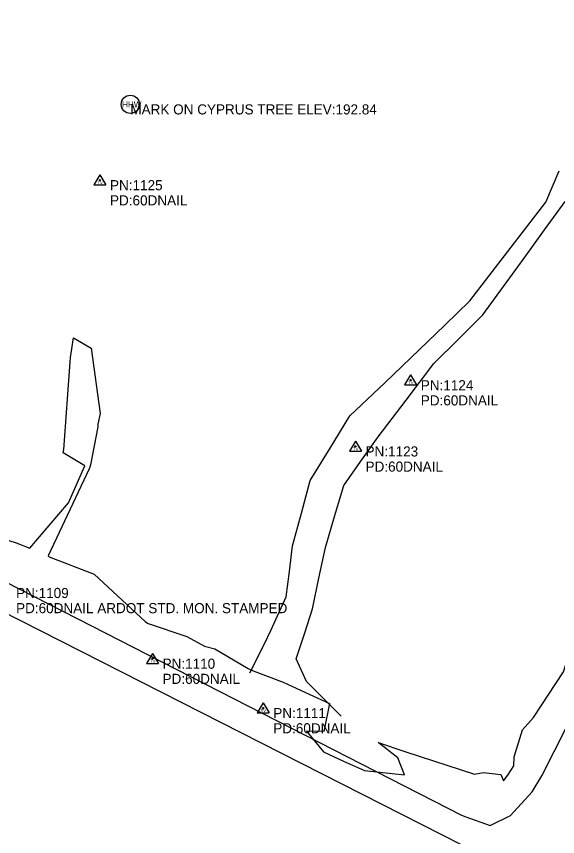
# Model space of a CAD drawing. Extents: x 1383673 to 1386849, y 1973501 to 1978801.
# Drawn here: x 1384772.1 to 1385039.6, y 1974564.7 to 1974970.6 of the extents above; entities that cross this region are included whole.
import ezdxf

# ---------------------------------------------------------------- set-up
doc = ezdxf.new("R2010")
doc.units = 0
for name, color, linetype in [('Level 8', 7, 'Continuous'), ('R_Draft', 7, 'Continuous'), ('R_Driveway', 7, 'Continuous'), ('R_Proposed Const Limits', 7, 'Continuous'), ('R_Proposed Road', 7, 'Continuous'), ('R_Shld', 7, 'Continuous'), ('S_STREAM', 7, 'Continuous')]:
    doc.layers.add(name, color=color, linetype=linetype)

msp = doc.modelspace()

# ---------------------------------------------------------------- linework, layer by layer
at = {"layer": 'Level 8'}
for p, q in [((1384813.33, 1974892.22), (1384810.32, 1974887.26)), ((1384813.33, 1974892.22), (1384816.27, 1974887.26)), ((1384810.32, 1974887.26), (1384816.27, 1974887.26)), ((1384966.98, 1974793.22), (1384963.97, 1974788.27)), ((1384966.98, 1974793.22), (1384969.93, 1974788.27)), ((1384963.97, 1974788.27), (1384969.93, 1974788.27)), ((1384939.68, 1974760.45), (1384936.67, 1974755.49)), ((1384939.68, 1974760.45), (1384942.63, 1974755.49)), ((1384936.67, 1974755.49), (1384942.63, 1974755.49)), ((1384839.32, 1974655.41), (1384836.31, 1974650.45)), ((1384839.32, 1974655.41), (1384842.27, 1974650.45)), ((1384836.31, 1974650.45), (1384842.27, 1974650.45)), ((1384894.06, 1974630.96), (1384891.05, 1974626)), ((1384894.06, 1974630.96), (1384897.01, 1974626)), ((1384891.05, 1974626), (1384897.01, 1974626))]:
    msp.add_line(p, q, dxfattribs=at)
for centre, radius in [((1384813.33, 1974889.6), 0.311), ((1384813.33, 1974889.6), 0.183), ((1384813.33, 1974889.6), 0.103), ((1384966.98, 1974790.61), 0.311), ((1384966.98, 1974790.61), 0.183), ((1384966.98, 1974790.61), 0.103), ((1384939.68, 1974757.84), 0.311), ((1384939.68, 1974757.84), 0.183), ((1384939.68, 1974757.84), 0.103), ((1384839.32, 1974652.8), 0.311), ((1384839.32, 1974652.8), 0.183), ((1384839.32, 1974652.8), 0.103), ((1384894.06, 1974628.35), 0.311), ((1384894.06, 1974628.35), 0.183), ((1384894.06, 1974628.35), 0.103)]:
    msp.add_circle(centre, radius, dxfattribs=at)
at = {"layer": 'R_Driveway'}
for points in [[(1383681.34, 1975246.82), (1384992.14, 1974575.32), (1384994.28, 1974574.56), (1385006.27, 1974570.28), (1385016.4, 1974575.19), (1385027.11, 1974586.91), (1385031.78, 1974594.79), (1385044.06, 1974618.83), (1385056.79, 1974646.33), (1385067.56, 1974674.42)], [(1385126, 1974491.57), (1385012.26, 1974550.38), (1383673.27, 1975231.65)]]:
    msp.add_lwpolyline(points, dxfattribs=at)
at = {"layer": 'R_Proposed Const Limits'}
for points in [[(1384887.44, 1974645.85), (1384894.77, 1974660.07), (1384897.9, 1974666.77), (1384905.43, 1974683.41), (1384907.03, 1974696), (1384908.62, 1974708.59), (1384913, 1974724.75), (1384917.38, 1974740.91), (1384927.14, 1974756.9), (1384936.89, 1974772.89), (1384954.16, 1974789.35), (1384971.43, 1974805.8), (1384983.81, 1974817.83), (1384996.18, 1974829.85), (1385005.58, 1974842.08), (1385014.98, 1974854.31), (1385024.37, 1974866.54), (1385033.77, 1974878.78), (1385040.46, 1974894.15)], [(1384932.65, 1974624.41), (1384915.5, 1974641.51), (1384910.44, 1974652.66), (1384914.43, 1974665.02), (1384918.42, 1974677.38), (1384921.64, 1974692.62), (1384924.86, 1974707.87), (1384929.41, 1974723.16), (1384933.95, 1974738.46), (1384942.42, 1974750.53), (1384950.89, 1974762.61), (1384964.69, 1974780.78), (1384978.49, 1974798.94), (1384990.62, 1974810.91), (1385002.74, 1974822.88), (1385012.9, 1974836.92), (1385023.06, 1974850.96), (1385033.23, 1974865), (1385043.39, 1974879.04)]]:
    msp.add_lwpolyline(points, dxfattribs=at)
at = {"layer": 'R_Proposed Road'}
msp.add_circle((1384828.39, 1974927.12), 4.5, dxfattribs=at)
at = {"layer": 'S_STREAM'}
for p, q in [((1384809.08, 1974806.52), (1384813.4, 1974774.11)), ((1384778.7, 1974707.55), (1384797.75, 1974729.95)), ((1384810.45, 1974694.65), (1384835.81, 1974671)), ((1384926.84, 1974630.57), (1384924, 1974616.69)), ((1384964.68, 1974606.62), (1384998.52, 1974595.65))]:
    msp.add_line(p, q, dxfattribs=at)
for points in [[(1384797.75, 1974729.95), (1384805.95, 1974748.22), (1384795.17, 1974754.62), (1384795.48, 1974756.3), (1384796.92, 1974776.78), (1384797.18, 1974779.1), (1384798.62, 1974799.56), (1384798.88, 1974801.9), (1384800.3, 1974811.64), (1384809.08, 1974806.52)], [(1384813.4, 1974774.11), (1384812.37, 1974768.81), (1384812.31, 1974767.5), (1384808.71, 1974748.72), (1384808.31, 1974747.6), (1384807.99, 1974746.71), (1384787.8, 1974703.72), (1384788.19, 1974703.11), (1384810.45, 1974694.65)], [(1384688.24, 1974743.55), (1384703.91, 1974739.09), (1384721.97, 1974736.82), (1384733.85, 1974732.46), (1384736.97, 1974733.01), (1384754.61, 1974719.2), (1384758.95, 1974714.84), (1384761.41, 1974713.33), (1384771.88, 1974710.18), (1384778.7, 1974707.55)], [(1384835.81, 1974671), (1384837.19, 1974670.18), (1384856.28, 1974663.8), (1384865, 1974658.91), (1384870.2, 1974657.67), (1384886.72, 1974647.88), (1384889.12, 1974646.74), (1384903.91, 1974641.12), (1384916.82, 1974635.26), (1384926.84, 1974630.57)], [(1384998.52, 1974595.65), (1385003.02, 1974596.47), (1385011.64, 1974595.42), (1385012.9, 1974592.33), (1385014.97, 1974595.19), (1385017.92, 1974599.74), (1385018.2, 1974604.18), (1385022.35, 1974617.56), (1385027.69, 1974623.6), (1385042.61, 1974646.35), (1385044.4, 1974652.06), (1385051.24, 1974665.13)], [(1384924, 1974616.69), (1384915.51, 1974616.98), (1384923.89, 1974606.67), (1384933.85, 1974602.03), (1384944.14, 1974597.42), (1384964, 1974595.29), (1384960.63, 1974603.71), (1384950.9, 1974611.33), (1384964.68, 1974606.62)]]:
    msp.add_lwpolyline(points, dxfattribs=at)

# ---------------------------------------------------------------- texts
at = {"layer": 'Level 8'}
for p in [(1384812.12, 1974887.59), (1384965.78, 1974788.6), (1384938.47, 1974755.83), (1384838.12, 1974650.79), (1384892.86, 1974626.34)]:
    msp.add_text('TV', height=1.5, dxfattribs=at).set_placement(p)
at = {"layer": 'R_Draft'}
for s, p in [('PN:1125', (1384818.33, 1974884.6)), ('PD:60DNAIL', (1384818.33, 1974877.1)), ('PN:1124', (1384971.98, 1974785.61)), ('PD:60DNAIL', (1384971.98, 1974778.11)), ('PN:1123', (1384944.68, 1974752.84)), ('PD:60DNAIL', (1384944.68, 1974745.34)), ('PN:1109', (1384771.89, 1974682.79)), ('PD:60DNAIL ARDOT STD. MON. STAMPED', (1384771.89, 1974675.29)), ('PN:1110', (1384844.32, 1974647.8)), ('PD:60DNAIL', (1384844.32, 1974640.3)), ('PN:1111', (1384899.06, 1974623.35)), ('PD:60DNAIL', (1384899.06, 1974615.85))]:
    msp.add_text(s, height=5, dxfattribs=at).set_placement(p)
at = {"layer": 'R_Proposed Road'}
msp.add_text('HHW', height=3, dxfattribs=at).set_placement((1384824.3, 1974925.62))
at = {"layer": 'R_Shld'}
msp.add_text('MARK ON CYPRUS TREE ELEV:192.84', height=5, dxfattribs=at).set_placement((1384828.39, 1974922.12))

doc.saveas('drawing.dxf')
